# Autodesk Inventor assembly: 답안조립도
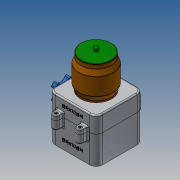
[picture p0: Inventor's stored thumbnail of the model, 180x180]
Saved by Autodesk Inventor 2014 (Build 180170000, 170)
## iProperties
Created: 2018-01
Part Number: 답안조립도
Document SubType Name: Assembly
Designer: 601-26
Author: 601-26
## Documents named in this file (9)
- C:\Users\601-26\Desktop\480108V1004\답안조립도.iam
- C:\Users\601-26\Desktop\480108V1004\본체.ipt
- C:\Users\601-26\Desktop\480108V1004\본체커버.ipt
- C:\Users\601-26\Desktop\480108V1004\볼트 M4x12.ipt
- C:\Users\601-26\Desktop\480108V1004\용기.ipt
- C:\Users\601-26\Desktop\480108V1004\핸들축.ipt
- C:\Users\601-26\Desktop\480108V1004\핸들.ipt
- C:\Users\601-26\Desktop\480108V1004\볼트 M3x12.ipt
- C:\Users\601-26\Desktop\480108V1004\용기캡.ipt
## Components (2 placed, 2 different names)
1. 핸들축:1 — 각도:1
2. 핸들:1
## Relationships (1: Angle 1)
- 각도:1 [Angle]: 핸들축:1
